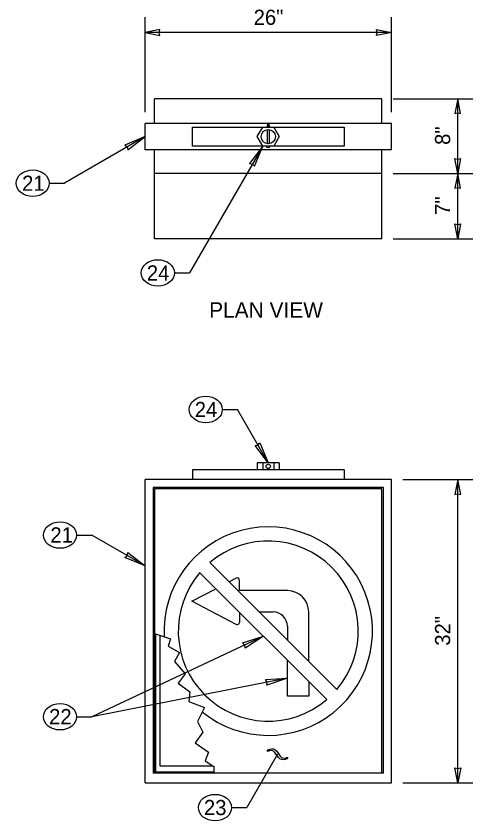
# Model space of a CAD drawing. Extents: x 99862 to 104211, y 98939 to 102076.
# Drawn here: x 100757 to 101239, y 100473 to 101322 of the extents above; entities that cross this region are included whole.
import ezdxf

# ---------------------------------------------------------------- set-up
doc = ezdxf.new("R2010")
doc.units = 0
for name, color, linetype in [('Level 15', 7, 'Continuous'), ('Level 20', 7, 'Continuous'), ('Level 22', 7, 'Continuous'), ('Level 24', 7, 'Continuous'), ('Level 25', 7, 'Continuous'), ('Level 27', 7, 'Continuous')]:
    doc.layers.add(name, color=color, linetype=linetype)

msp = doc.modelspace()

# ---------------------------------------------------------------- linework, layer by layer
at = {"layer": 'Level 15'}
for p, q in [((100893.02, 101220.82), (100893.02, 101321.03)), ((101153.02, 101220.82), (101153.02, 101321.03)), ((101153.02, 101305.03), (100893.02, 101305.03)), ((101155.02, 101235.07), (101239, 101235.07)), ((101223, 101156.32), (101223, 101235.07)), ((100893.02, 101195.07), (100807.86, 101145.9)), ((101017.24, 101185.07), (100939.98, 101051.25)), ((101155.02, 101156.32), (101239, 101156.32)), ((101223, 101087.41), (101223, 101156.32)), ((100791.86, 101145.9), (100807.86, 101145.9)), ((101155.02, 101087.41), (101239, 101087.41)), ((100923.98, 101051.25), (100939.98, 101051.25)), ((100974.52, 100907.12), (100990.52, 100907.12)), ((101023.02, 100850.83), (100990.52, 100907.12)), ((101165.02, 100833.33), (101239.02, 100833.33)), ((101223.02, 100513.33), (101223.02, 100833.33)), ((100820.72, 100774.68), (100836.72, 100774.68)), ((100893.02, 100742.18), (100836.72, 100774.68)), ((101017.93, 100667.81), (100836.72, 100582.99)), ((101043.19, 100623.64), (100836.72, 100582.99)), ((100820.72, 100582.99), (100836.72, 100582.99)), ((101023.08, 100548.12), (101025.1, 100548.86)), ((101025.1, 100548.86), (101026.86, 100549.13)), ((101026.86, 100549.13), (101028.46, 100548.96)), ((101028.46, 100548.96), (101029.99, 100548.31)), ((101032.83, 100543.34), (101000.33, 100487.05)), ((101022.03, 100546.29), (101023.08, 100548.12)), ((101025.6, 100547.22), (101022.03, 100546.29)), ((101027.25, 100547.16), (101025.6, 100547.22)), ((101028.59, 100546.68), (101027.25, 100547.16)), ((101029.75, 100545.73), (101028.59, 100546.68)), ((101031.13, 100543.74), (101029.75, 100545.73)), ((101029.99, 100548.31), (101031.92, 100546.77)), ((101033.65, 100540.12), (101031.13, 100543.74)), ((101031.92, 100546.77), (101034.19, 100543.36)), ((101034.19, 100543.36), (101035.65, 100541.28)), ((101035.65, 100541.28), (101037.11, 100540.02)), ((101041.41, 100539.65), (101043.72, 100540.38)), ((101043.72, 100540.39), (101042.66, 100538.56)), ((101035.74, 100538.37), (101033.65, 100540.12)), ((101037.36, 100537.69), (101035.74, 100538.37)), ((101037.11, 100540.02), (101038.34, 100539.52)), ((101039.06, 100537.5), (101037.36, 100537.69)), ((101038.34, 100539.52), (101039.7, 100539.38)), ((101040.83, 100537.79), (101039.06, 100537.5)), ((101039.7, 100539.38), (101041.41, 100539.65)), ((101042.66, 100538.55), (101040.83, 100537.79)), ((101165.02, 100513.33), (101239.02, 100513.33)), ((100984.33, 100487.05), (101000.33, 100487.05))]:
    msp.add_line(p, q, dxfattribs=at)
for points in [[(100893.02, 101305.03), (100908.74, 101301.95), (100908.01, 101305.03), (100908.74, 101308.12)], [(101153.02, 101305.03), (101137.29, 101301.95), (101138.02, 101305.03), (101137.29, 101308.12)], [(101223, 101235.07), (101219.92, 101219.35), (101223, 101220.07), (101226.09, 101219.35)], [(100893.02, 101195.07), (100871.75, 101186.24), (100874.16, 101184.18), (100874.74, 101181.07)], [(101017.24, 101185.07), (101003.24, 101166.79), (101006.36, 101166.21), (101008.41, 101163.81)], [(101223, 101156.32), (101219.92, 101172.05), (101223, 101171.32), (101226.09, 101172.05)], [(101223, 101156.32), (101219.92, 101140.6), (101223, 101141.32), (101226.09, 101140.6)], [(101223, 101087.41), (101219.92, 101103.14), (101223, 101102.41), (101226.09, 101103.14)], [(101023.02, 100850.83), (101009.02, 100869.11), (101012.13, 100869.68), (101014.19, 100872.09)], [(101223.02, 100833.33), (101219.93, 100817.6), (101223.02, 100818.33), (101226.1, 100817.6)], [(100893.02, 100742.18), (100871.75, 100751), (100874.16, 100753.06), (100874.74, 100756.18)], [(101017.93, 100667.81), (100998.52, 100655.43), (100998.21, 100658.58), (100995.98, 100660.83)], [(101043.19, 100623.64), (101021.36, 100616.3), (101021.82, 100619.43), (101020.21, 100622.16)], [(101223.02, 100513.33), (101219.93, 100529.05), (101223.02, 100528.32), (101226.1, 100529.05)]]:
    msp.add_lwpolyline(points, close=True, dxfattribs=at)
at = {"layer": 'Level 20'}
for centre in [(100774.36, 101145.9), (100906.48, 101051.25), (100957.02, 100907.12), (100803.22, 100774.68), (100803.22, 100582.99), (100966.83, 100487.05)]:
    msp.add_ellipse(centre, major_axis=(-17.5, 0), ratio=0.8, dxfattribs=at)
at = {"layer": 'Level 22'}
for p, q in [((100903.02, 101208.82), (100903.02, 101235.07)), ((101143.02, 101235.07), (100903.02, 101235.07)), ((101143.02, 101208.82), (101143.02, 101235.07)), ((100893.02, 101181.32), (100893.02, 101208.82)), ((101022.73, 101208.82), (100893.02, 101208.82)), ((100943.02, 101185.07), (100943.02, 101205.07)), ((100943.02, 101205.07), (101017.24, 101205.07)), ((101153.02, 101208.82), (101023.3, 101208.82)), ((101028.79, 101205.07), (101103.02, 101205.07)), ((101103.02, 101205.07), (101103.02, 101185.07)), ((101153.02, 101181.32), (101153.02, 101208.82)), ((101153.02, 101181.32), (100893.02, 101181.32)), ((100903.02, 101087.41), (100903.02, 101181.32)), ((101017.24, 101185.07), (100943.02, 101185.07)), ((101103.02, 101185.07), (101028.79, 101185.07)), ((101143.02, 101087.41), (101143.02, 101181.32)), ((101143.02, 101156.32), (100903.02, 101156.32)), ((101143.02, 101087.41), (100903.02, 101087.41)), ((101103.02, 100843.33), (100943.02, 100843.33)), ((100943.02, 100843.33), (100943.02, 100833.33)), ((101103.02, 100843.33), (101103.02, 100833.33)), ((101153.02, 100833.33), (100893.02, 100833.33)), ((100893.02, 100513.33), (100893.02, 100833.33)), ((101153.02, 100513.33), (101153.02, 100833.33)), ((100901.52, 100824.83), (100901.52, 100523.33)), ((101144.52, 100824.83), (100901.52, 100824.83)), ((100903.02, 100823.33), (100903.02, 100523.33)), ((101143.02, 100823.33), (100903.02, 100823.33)), ((101143.02, 100523.33), (101143.02, 100823.33)), ((101144.52, 100523.33), (101144.52, 100824.83)), ((100904.27, 100524.58), (100904.27, 100670.49)), ((101144.52, 100523.33), (100901.52, 100523.33)), ((100965.47, 100524.58), (100904.27, 100524.58)), ((100893.02, 100513.33), (101153.02, 100513.33))]:
    msp.add_line(p, q, dxfattribs=at)
msp.add_lwpolyline([(100903.02, 100670.92), (100919.91, 100665.05), (100917.33, 100657.6), (100929.37, 100650.77), (100924.02, 100641.35), (100935.2, 100628.25), (100927.96, 100618.39), (100940.32, 100609.31), (100939.02, 100598.88), (100955.62, 100592.83), (100948.19, 100577.83), (100954.11, 100566.7), (100946.03, 100555.42), (100959.98, 100545.43), (100956.32, 100536.33), (100965.57, 100530.5), (100965.45, 100523.33)], dxfattribs=at)
at = {"layer": 'Level 24'}
for p, q in [((100909.02, 100530.91), (100909.02, 100668.84)), ((100964.92, 100530.91), (100909.02, 100530.91))]:
    msp.add_line(p, q, dxfattribs=at)
at = {"layer": 'Level 25'}
for p, q in [((101011.47, 101195.07), (101017.24, 101205.07)), ((101017.24, 101205.07), (101028.79, 101205.07)), ((101022.72, 101207.35), (101021.77, 101207.35)), ((101021.77, 101207.35), (101021.77, 101205.07)), ((101024.27, 101207.35), (101023.32, 101207.35)), ((101024.27, 101205.07), (101024.27, 101207.35)), ((101028.79, 101205.07), (101034.56, 101195.07)), ((101017.24, 101185.07), (101011.47, 101195.07)), ((101021.77, 101202.47), (101021.77, 101187.68)), ((101024.27, 101187.68), (101024.27, 101202.47)), ((101034.56, 101195.07), (101028.79, 101185.07)), ((101028.79, 101185.07), (101017.24, 101185.07)), ((101017.24, 100850.83), (101011.47, 100850.83)), ((101011.47, 100850.83), (101011.47, 100843.33)), ((101017.24, 100850.83), (101017.24, 100843.33)), ((101028.79, 100850.83), (101017.24, 100850.83)), ((101034.56, 100850.83), (101028.79, 100850.83)), ((101028.79, 100850.83), (101028.79, 100843.33)), ((101034.56, 100850.83), (101034.56, 100843.33))]:
    msp.add_line(p, q, dxfattribs=at)
for centre, radius in [((101023.02, 101195.07), 7.5), ((101023.02, 100847.08), 2.31)]:
    msp.add_circle(centre, radius, dxfattribs=at)
msp.add_arc((101023.02, 101186.03), 2.5, 202.48197, 337.51803, dxfattribs=at)
for points in [[(101022.72, 101206.74), (101022.66, 101206.71), (101022.62, 101206.68), (101022.46, 101206.52), (101022.39, 101206.36), (101022.39, 101206.03), (101022.46, 101205.87), (101022.69, 101205.64), (101022.85, 101205.57), (101023.18, 101205.57), (101023.34, 101205.64), (101023.57, 101205.87), (101023.64, 101206.03), (101023.64, 101206.2)], [(101022.72, 101206.18), (101022.72, 101206.2), (101022.72, 101206.26), (101022.72, 101206.69), (101022.72, 101207.63), (101022.72, 101208.26), (101022.72, 101208.44), (101022.72, 101208.54), (101022.72, 101208.56), (101022.72, 101208.73)], [(101023.32, 101208.73), (101023.32, 101208.18), (101023.32, 101207.89), (101023.32, 101207.5), (101023.32, 101207.31), (101023.32, 101207.17), (101023.32, 101207.1), (101023.32, 101206.19)], [(101023.64, 101206.2), (101023.64, 101206.36), (101023.57, 101206.52), (101023.42, 101206.68), (101023.37, 101206.71), (101023.32, 101206.74)]]:
    msp.add_open_spline(points, degree=3, dxfattribs=at)
at = {"layer": 'Level 27'}
for p, q in [((100981.67, 100725.28), (100961.35, 100745.6)), ((100967.72, 100718.01), (100950.75, 100734.99)), ((100989.01, 100729.1), (100981.67, 100725.28)), ((101013.45, 100693.5), (100981.66, 100725.29)), ((100992.67, 100716), (100992.67, 100726.88)), ((100942.24, 100704.75), (100967.72, 100718.01)), ((100992.67, 100693.07), (100967.72, 100718.01)), ((100967.72, 100718.01), (100967.72, 100718.01)), ((101043.19, 100716), (100992.67, 100716)), ((100989.01, 100680.4), (100942.24, 100704.75)), ((101043.19, 100642.55), (100992.67, 100693.07)), ((100992.67, 100693.07), (100992.67, 100682.62)), ((101013.45, 100693.5), (101028.19, 100693.5)), ((101043.19, 100663.76), (101013.45, 100693.5)), ((101065.69, 100641.26), (101065.69, 100693.5)), ((101043.19, 100678.5), (101043.19, 100663.76)), ((101065.69, 100641.26), (101043.21, 100663.74)), ((101065.69, 100620.05), (101043.19, 100642.55)), ((101043.19, 100604.73), (101043.19, 100642.55)), ((101095.29, 100611.66), (101065.69, 100641.26)), ((101084.68, 100601.06), (101065.69, 100620.05)), ((101065.69, 100620.05), (101065.69, 100604.73)), ((101065.69, 100604.73), (101043.19, 100604.73))]:
    msp.add_line(p, q, dxfattribs=at)
for centre, radius, start, end in [((101023.02, 101208.73), 0.3, 360, 180), ((101023.02, 101206.19), 0.3, 180, 0), ((101023.02, 100673.33), 110, 230.68991, 183.09202), ((101023.02, 100673.33), 95, 319.52806, 130.47194), ((101023.02, 100673.33), 95, 139.52806, 310.47194), ((100990.17, 100726.88), 2.5, 0, 117.49881), ((101043.19, 100693.5), 22.5, 0, 90), ((101028.19, 100678.5), 15, 0, 90), ((100990.17, 100682.62), 2.5, 242.50119, 0)]:
    msp.add_arc(centre, radius, start, end, dxfattribs=at)

# ---------------------------------------------------------------- texts
at = {"layer": 'Level 20'}
for s, height, p in [('26"', 16, (101007.61, 101313.03)), ('21', 16, (100763.18, 101137.9)), ('24', 16, (100894.85, 101043.25)), ('PLAN VIEW', 16.5, (100960.6, 101003.92)), ('24', 16, (100945.39, 100899.12)), ('21', 16, (100793.03, 100766.81)), ('22', 16, (100791.68, 100575.12)), ('23', 16, (100955.13, 100479.18))]:
    msp.add_text(s, height=height, dxfattribs=at).set_placement(p)
for s, p in [('8"', (101215, 101186.33)), ('7"', (101215, 101112.5)), ('32"', (101215.02, 100657.92))]:
    msp.add_text(s, height=16, rotation=90, dxfattribs=at).set_placement(p)

doc.saveas('drawing.dxf')
